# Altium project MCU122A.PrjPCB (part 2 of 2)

## Sheet MCU122A_WM2_ESD.SchDoc
size A3; Date: Not shown in title block; ApprovedBy: Not shown in title block; CheckedBy: Not shown in title block; Author: Not shown in title block; CompanyName: Not shown in title block; Engineer: Not shown in title block; Organization: Not shown in title block; Address1: Not shown in title block; Address2: Not shown in title block; Address3: Not shown in title block; Address4: Not shown in title block; DocumentNumber: 1; Revision: Use project parameter SCH_Rev; SheetNumber: 6; SheetTotal: 8; PageSetup: Record=PageOptions¦CenterHorizontal=True¦CenterVertical=True¦PrintScale=0.69¦XCorrection=1.00¦YCorrection=1.00¦PrintKind=0¦BorderSize=5000000¦LeftOffset=0¦BottomOffset=0¦Orientation=2¦PaperLength=1000¦PaperWidth=1000¦Scale=100¦PaperSource=15¦PrintQuality=600¦MediaType=1¦DitherType=10¦PaperKind=Letter¦PrintScaleMode=1
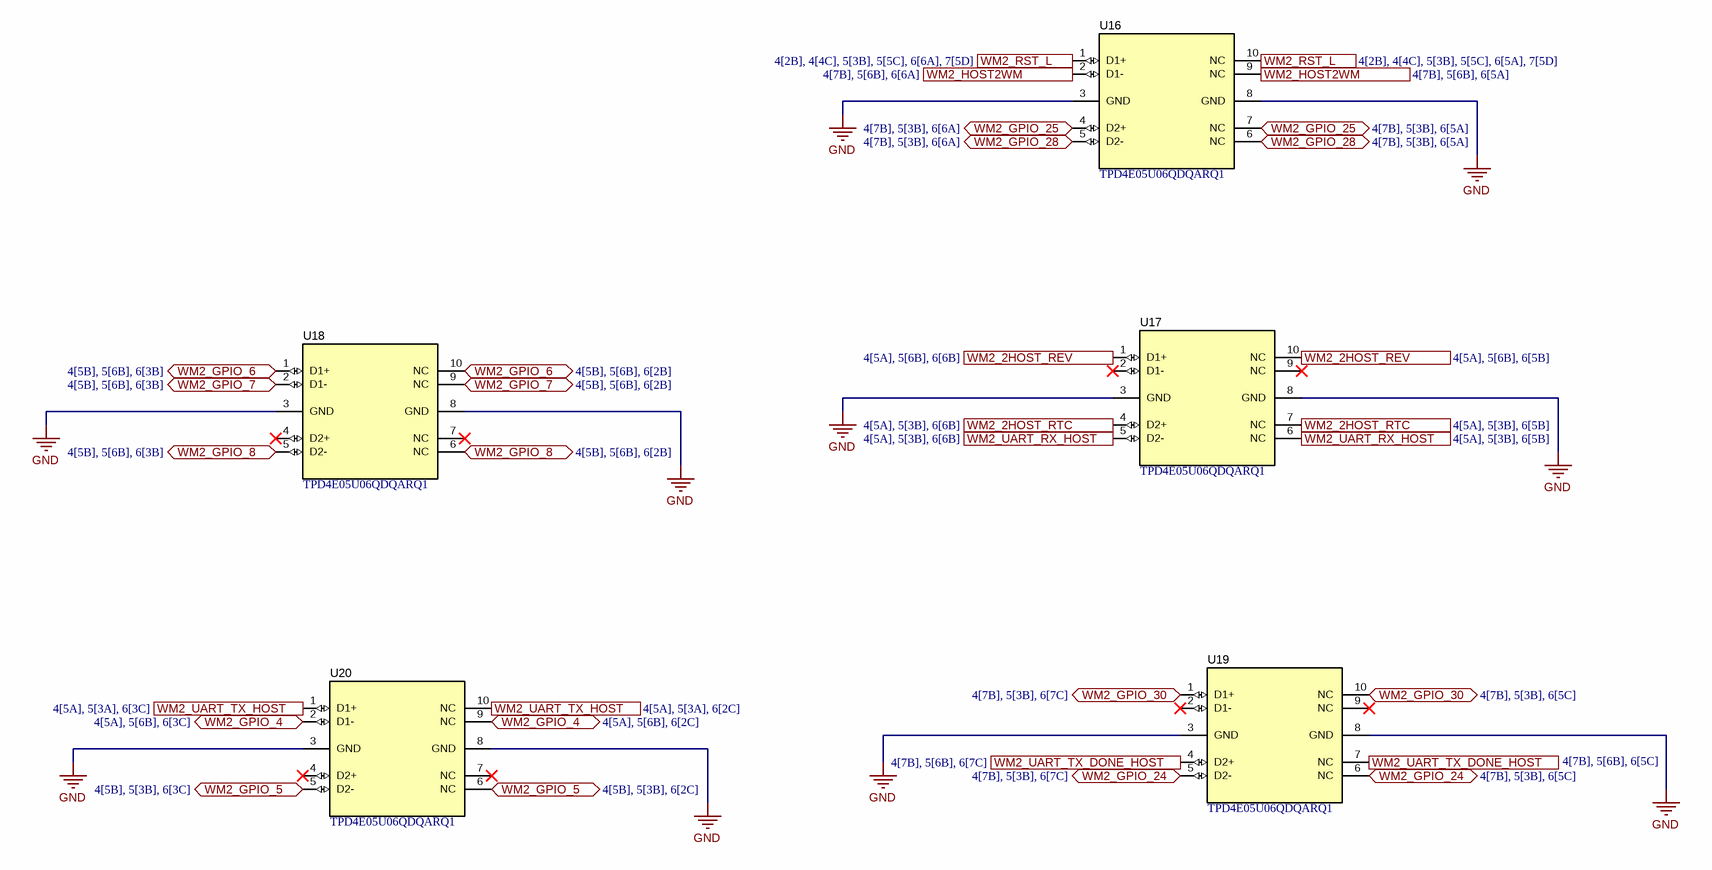
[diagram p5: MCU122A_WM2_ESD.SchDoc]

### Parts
U16  TPD4E05U06QDQARQ1  [DQA0010A]
U17  TPD4E05U06QDQARQ1  [DQA0010A]
U18  TPD4E05U06QDQARQ1  [DQA0010A]
U19  TPD4E05U06QDQARQ1  [DQA0010A]
U20  TPD4E05U06QDQARQ1  [DQA0010A]

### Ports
WM2_2HOST_REV (out, see 4[5A], 5[6B], 6[5B]), WM2_2HOST_REV (out, see 4[5A], 5[6B], 6[6B]), WM2_2HOST_RTC (out, see 4[5A], 5[3B], 6[5B]), WM2_2HOST_RTC (out, see 4[5A], 5[3B], 6[6B]), WM2_GPIO_4 (bidir, see 4[5A], 5[6B], 6[2C]), WM2_GPIO_4 (bidir, see 4[5A], 5[6B], 6[3C]), WM2_GPIO_5 (bidir, see 4[5B], 5[3B], 6[2C]), WM2_GPIO_5 (bidir, see 4[5B], 5[3B], 6[3C]), WM2_GPIO_6 (bidir, see 4[5B], 5[6B], 6[2B]), WM2_GPIO_6 (bidir, see 4[5B], 5[6B], 6[3B]), WM2_GPIO_7 (bidir, see 4[5B], 5[6B], 6[2B]), WM2_GPIO_7 (bidir, see 4[5B], 5[6B], 6[3B]), WM2_GPIO_8 (bidir, see 4[5B], 5[6B], 6[2B]), WM2_GPIO_8 (bidir, see 4[5B], 5[6B], 6[3B]), WM2_GPIO_24 (bidir, see 4[7B], 5[3B], 6[5C]), WM2_GPIO_24 (bidir, see 4[7B], 5[3B], 6[7C]), WM2_GPIO_25 (bidir, see 4[7B], 5[3B], 6[5A]), WM2_GPIO_25 (bidir, see 4[7B], 5[3B], 6[6A]), WM2_GPIO_28 (bidir, see 4[7B], 5[3B], 6[5A]), WM2_GPIO_28 (bidir, see 4[7B], 5[3B], 6[6A]), WM2_GPIO_30 (bidir, see 4[7B], 5[3B], 6[5C]), WM2_GPIO_30 (bidir, see 4[7B], 5[3B], 6[7C]), WM2_HOST2WM (out, see 4[7B], 5[6B], 6[5A]), WM2_HOST2WM (out, see 4[7B], 5[6B], 6[6A]), WM2_RST_L (out, see 4[2B], 4[4C], 5[3B], 5[5C], 6[5A], 7[5D]), WM2_RST_L (out, see 4[2B], 4[4C], 5[3B], 5[5C], 6[6A], 7[5D]), WM2_UART_RX_HOST (out, see 4[5A], 5[3B], 6[5B]), WM2_UART_RX_HOST (out, see 4[5A], 5[3B], 6[6B]), WM2_UART_TX_DONE_HOST (out, see 4[7B], 5[6B], 6[5C]), WM2_UART_TX_DONE_HOST (out, see 4[7B], 5[6B], 6[7C]), WM2_UART_TX_HOST (out, see 4[5A], 5[3A], 6[2C]), WM2_UART_TX_HOST (out, see 4[5A], 5[3A], 6[3C])

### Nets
GND: U16.3(GND) U16.8(GND) U17.3(GND) U17.8(GND) U18.3(GND) U18.8(GND) U19.3(GND) U19.8(GND) U20.3(GND) U20.8(GND)
WM2_2HOST_REV: U17.1(D1+) U17.10(NC) ; port WM2_2HOST_REV
WM2_2HOST_RTC: U17.4(D2+) U17.7(NC) ; port WM2_2HOST_RTC
WM2_GPIO_4: U20.2(D1-) U20.9(NC) ; port WM2_GPIO_4
WM2_GPIO_5: U20.5(D2-) U20.6(NC) ; port WM2_GPIO_5
WM2_GPIO_6: U18.1(D1+) U18.10(NC) ; port WM2_GPIO_6
WM2_GPIO_7: U18.2(D1-) U18.9(NC) ; port WM2_GPIO_7
WM2_GPIO_8: U18.5(D2-) U18.6(NC) ; port WM2_GPIO_8
WM2_GPIO_24: U19.5(D2-) U19.6(NC) ; port WM2_GPIO_24
WM2_GPIO_25: U16.4(D2+) U16.7(NC) ; port WM2_GPIO_25
WM2_GPIO_28: U16.5(D2-) U16.6(NC) ; port WM2_GPIO_28
WM2_GPIO_30: U19.1(D1+) U19.10(NC) ; port WM2_GPIO_30
WM2_HOST2WM: U16.2(D1-) U16.9(NC) ; port WM2_HOST2WM
WM2_RST_L: U16.1(D1+) U16.10(NC) ; port WM2_RST_L
WM2_UART_RX_HOST: U17.5(D2-) U17.6(NC) ; port WM2_UART_RX_HOST
WM2_UART_TX_DONE_HOST: U19.4(D2+) U19.7(NC) ; port WM2_UART_TX_DONE_HOST
WM2_UART_TX_HOST: U20.1(D1+) U20.10(NC) ; port WM2_UART_TX_HOST

Not connected (* = marked no-connect by the designer): U17 2(D1-)* 9(NC)*; U18 4(D2+)* 7(NC)*; U19 2(D1-)* 9(NC)*; U20 4(D2+)* 7(NC)*

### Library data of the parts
U16-U20 = CMP-0073599-3: Automotive 4-Channel ESD Protection Solution for SuperSpeed (up to 5 Gbps) Interface, DQA0010A (USON-10); Manufacturer: Texas Instruments; SizeZ_mm: 0.55; SizeX_mm: 1.0; SizeY_mm: 2.5; CompType: IC; SizeAreaWB_mm2: 7.0; AEC Category: Q200; AEC Qualified: Y

## Sheet MCU122A_Connector_PWR.SchDoc
size A3; Date: Not shown in title block; ApprovedBy: Not shown in title block; CheckedBy: Not shown in title block; Author: Not shown in title block; CompanyName: Not shown in title block; Engineer: Not shown in title block; Organization: Not shown in title block; Address1: Not shown in title block; Address2: Not shown in title block; Address3: Not shown in title block; Address4: Not shown in title block; DocumentNumber: 1; Revision: Use project parameter SCH_Rev; SheetNumber: 7; SheetTotal: 8; PageSetup: Record=PageOptions¦CenterHorizontal=True¦CenterVertical=True¦PrintScale=0.69¦XCorrection=1.00¦YCorrection=1.00¦PrintKind=0¦BorderSize=5000000¦LeftOffset=0¦BottomOffset=0¦Orientation=2¦PaperLength=1000¦PaperWidth=1000¦Scale=100¦PaperSource=15¦PrintQuality=600¦MediaType=1¦DitherType=10¦PaperKind=Letter¦PrintScaleMode=1
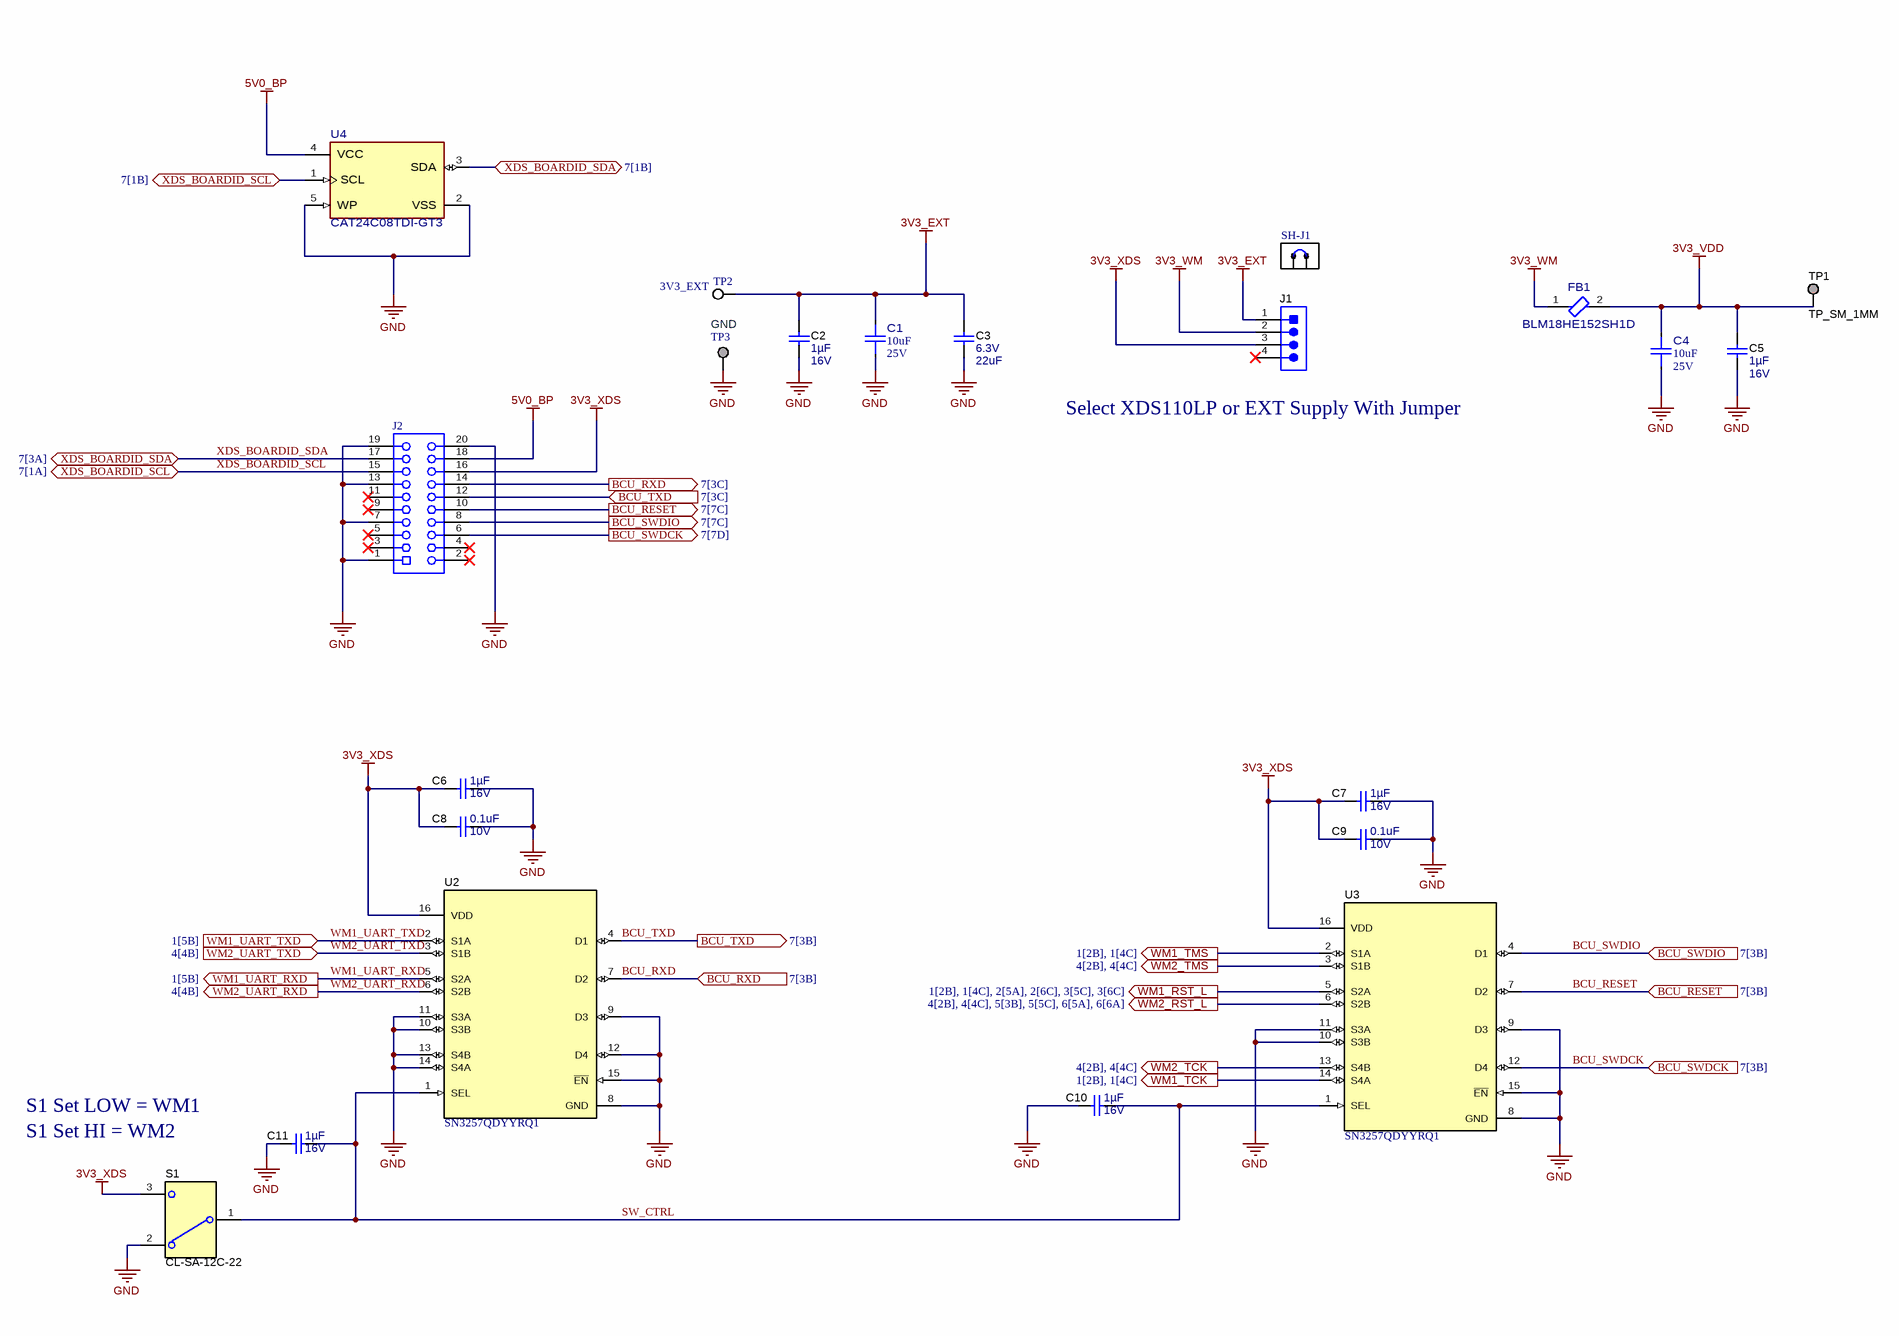
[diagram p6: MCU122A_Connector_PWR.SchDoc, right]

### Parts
C1  ValueDisplayed: 10uF  VDC_V: 25V  [FP-GCM32ER71E106MA57L_1210-MFG]  (hidden comment: GCM32ER71E106MA57L)
C2  Cap_F: 1µF  VDC_V: 16V  [0603]  (hidden comment: GCM188R71C105KA64D)
C3  VDC_V: 6.3V  ValueDisplayed: 22uF  [0805_HV]  (hidden comment: GCM21BD70J226ME36L)
C4  ValueDisplayed: 10uF  VDC_V: 25V  [FP-GCM32ER71E106MA57L_1210-MFG]  (hidden comment: GCM32ER71E106MA57L)
C5  Cap_F: 1µF  VDC_V: 16V  [0603]  (hidden comment: GCM188R71C105KA64D)
C6  Cap_F: 1µF  VDC_V: 16V  [0603]  (hidden comment: GCM188R71C105KA64D)
C7  Cap_F: 1µF  VDC_V: 16V  [0603]  (hidden comment: GCM188R71C105KA64D)
C8  VDC_V: 10V  ValueDisplayed: 0.1uF  [0402]  (hidden comment: GCM155R71A104KA55D)
C9  VDC_V: 10V  ValueDisplayed: 0.1uF  [0402]  (hidden comment: GCM155R71A104KA55D)
C10  Cap_F: 1µF  VDC_V: 16V  [0603]  (hidden comment: GCM188R71C105KA64D)
C11  Cap_F: 1µF  VDC_V: 16V  [0603]  (hidden comment: GCM188R71C105KA64D)
FB1  BLM18HE152SH1D  [FP-BLM18HE152SH1D_0603-MFG]
J1  TSW-104-07-G-S  [TSW-104-07-G-S]  (value not drawn)
J2  SFH11-PBPC-D10-RA-BK  [Sullins_SFH11-xxxC-D10-RA]  (value not drawn)
S1  CL-SA-12C-22  [SW_CL-SA-12C-22]
SH-J1  SNT-100-BK-G  [SNT-100-BK-G]  (value not drawn)
TP1  TP_SM_1MM  [TP_SM_1MM]  (no BOM)
TP2  Note: 3V3_EXT  [Keystone5012]  (hidden comment: 5012)
TP3  GND  [Keystone1598-2]
U2  SN3257QDYYRQ1  [DYY0016A]
U3  SN3257QDYYRQ1  [DYY0016A]
U4  CAT24C08TDI-GT3  [FP-CAT24C08TDI-GT3_TSOT-23-5-IPC_C]

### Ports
BCU_RESET (in, see 7[3B]), BCU_RESET (out, see 7[7C]), BCU_RXD (in, see 7[3B]), BCU_RXD (out, see 7[3C]), BCU_SWDCK (in, see 7[3B]), BCU_SWDCK (out, see 7[7D]), BCU_SWDIO (in, see 7[3B]), BCU_SWDIO (out, see 7[7C]), BCU_TXD (in, see 7[3C]), BCU_TXD (out, see 7[3B]), WM1_RST_L (out, see 1[2B], 1[4C], 2[5A], 2[6C], 3[5C], 3[6C]), WM1_TCK (out, see 1[2B], 1[4C]), WM1_TMS (out, see 1[2B], 1[4C]), WM1_UART_RXD (out, see 1[5B]), WM1_UART_TXD (in, see 1[5B]), WM2_RST_L (out, see 4[2B], 4[4C], 5[3B], 5[5C], 6[5A], 6[6A]), WM2_TCK (out, see 4[2B], 4[4C]), WM2_TMS (out, see 4[2B], 4[4C]), WM2_UART_RXD (out, see 4[4B]), WM2_UART_TXD (in, see 4[4B]), XDS_BOARDID_SCL (bidir, see 7[1A]), XDS_BOARDID_SCL (bidir, see 7[1B]), XDS_BOARDID_SDA (bidir, see 7[1B]), XDS_BOARDID_SDA (bidir, see 7[3A])

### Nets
3V3_EXT: C1.2 C2.1 C3.1 J1.1 TP2.1
3V3_VDD: C4.2 C5.1 FB1.2 TP1.1
3V3_WM: FB1.1 J1.2
3V3_XDS: C6.2 C7.2 C8.2 C9.2 J1.3 J2.16 S1.3 U2.16(VDD) U3.16(VDD)
5V0_BP: J2.18 U4.4(VCC)
GND: C1.1 C2.2 C3.2 C4.1 C5.2 C6.1 C7.1 C8.1 C9.1 C10.2 C11.2 J2.1 J2.7 J2.13 J2.19 J2.20 S1.2 TP3.1 U2.8(GND) U2.9(D3) U2.10(S3B) U2.11(S3A) U2.12(D4) U2.13(S4B) U2.14(S4A) U2.15(~{EN}) U3.8(GND) U3.9(D3) U3.10(S3B) U3.11(S3A) U3.15(~{EN}) U4.2(VSS) U4.5(WP)
BCU_RESET: J2.10 U3.7(D2) ; port BCU_RESET
BCU_RXD: J2.14 U2.7(D2) ; port BCU_RXD
BCU_SWDCK: J2.6 U3.12(D4) ; port BCU_SWDCK
BCU_SWDIO: J2.8 U3.4(D1) ; port BCU_SWDIO
BCU_TXD: J2.12 U2.4(D1) ; port BCU_TXD
SW_CTRL: C10.1 C11.1 S1.1 U2.1(SEL) U3.1(SEL)
WM1_RST_L: U3.5(S2A) ; port WM1_RST_L
WM1_TCK: U3.14(S4A) ; port WM1_TCK
WM1_TMS: U3.2(S1A) ; port WM1_TMS
WM1_UART_RXD: U2.5(S2A) ; port WM1_UART_RXD
WM1_UART_TXD: U2.2(S1A) ; port WM1_UART_TXD
WM2_RST_L: U3.6(S2B) ; port WM2_RST_L
WM2_TCK: U3.13(S4B) ; port WM2_TCK
WM2_TMS: U3.3(S1B) ; port WM2_TMS
WM2_UART_RXD: U2.6(S2B) ; port WM2_UART_RXD
WM2_UART_TXD: U2.3(S1B) ; port WM2_UART_TXD
XDS_BOARDID_SCL: J2.15 U4.1(SCL) ; port XDS_BOARDID_SCL
XDS_BOARDID_SDA: J2.17 U4.3(SDA) ; port XDS_BOARDID_SDA

Not connected (* = marked no-connect by the designer): J1 4*; J2 2* 3* 4* 5* 9* 11*

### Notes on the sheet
- (near J1) Select XDS110LP or EXT Supply With Jumper
- S1 Set LOW = WM1
- S1 Set HI = WM2

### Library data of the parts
C1 C4 = CMP-0037171-1: Ceramic Capacitor for Automotive 10uF ±20% 25VDC X7R 1210 Embossed T/R; Manufacturer: Murata; AEC Grade: Grade 1; AEC Qualified: Yes; Cap_F: 10µF; SizeZ_mm: 2.7mm; TempCo: 15%; Value: 10µF
C2 C5-C7 C10 C11 = CMP-0007136-5: CAP, CERM, 1 uF, 16 V, +/- 10%, X7R, AEC-Q200 Grade 1, 0603; Manufacturer: MuRata; TaMin_C: -55°C; Polarized: N; SizeAreaWB_mm2: 4.68; Value1: Unknown; U/M: EA; Value: 1uF; TaMax_C: 125°C; SizeZ_mm: 1; SizeX_mm: 1.6; SizeY_mm: 0.8; SizeArea_mm2: 1.28; AEC Qualified: Y; AEC Category: Q200
C3 = CMP-0008015-1: CAP, CERM, 22 uF, 6.3 V, +/- 20%, X7T, AEC-Q200 Grade 1, 0805; Manufacturer: MuRata; TaMin_C: -55°C; Polarized: N; SizeAreaWB_mm2: 6.75; Value1: Unknown; U/M: EA; Value: 22uF; TaMax_C: 125°C; SizeZ_mm: 1.45; SizeX_mm: 2; SizeY_mm: 1.25; Cap_Case: 0805; SizeArea_mm2: 2.5; AEC Qualified: Y; Cap_F: 22µF; AEC Grade: 1; AEC Category: Q200
C8 C9 = CMP-0006350-2: CAP, CERM, 0.1 uF, 10 V, +/- 10%, X7R, AEC-Q200 Grade 1, 0402; Manufacturer: MuRata; TaMin_C: -55°C; Polarized: N; SizeAreaWB_mm2: 3; Value1: Unknown; U/M: EA; Value: 0.1uF; TaMax_C: 125°C; SizeZ_mm: 0.6; SizeX_mm: 1; SizeY_mm: 0.5; AEC Qualified: Y; Cap_F: 100nF; AEC Category: Q200
FB1 = CMP-0092703-1: Chip Ferrite Bead, 0603, 1500Ω @ 100MHz, 0.5Ω, 25%, 500mA; Manufacturer: Murata; AEC Grade: Grade 1; AEC Qualified: Yes; SizeZ_mm: 0.95mm; DCR_ohm: 0.5
J1 = CMP-0075409-2: Header, 100mil, 4x1, Gold, TH; Manufacturer: Samtec; Pitch_mm: 2.54; Cert_VDE: N; Gender: Male; Cert_CSA: Y; Voltage_V: 550V; Green_REACh: Passed; Current_A: 6.3A; Green_Lifecycle: Active; Row_Count: 1
J2 = CMP-0074634-1: Receptacle, 2.54mm, 10x2, Gold, R/A, TH; Manufacturer: Sullins Connector Solutions; CNHeader: False; Current_A: 3A; Gender: Female; Voltage_V: 1kV; CompType: Socket Strip; Row_Count: 2; Pitch_mm: 2.54; CT: True; Cert_UL: Y
S1 = CMP-0078235-1: Switch, SPDT, On-On, 0.5 A, 12 VDC, TH; Manufacturer: NIDEC SEIMITSU; SizeAreaWB_mm2: 54.48; SizeArea_mm2: 25.4; SizeZ_mm: 6.7; SizeY_mm: 2.54; VDC_V: 12V; CurrentRating_mA: 500A; PositionCount: 2; SizeX_mm: 10
SH-J1 = CMP-0003623-3: Shunt, 100mil, Gold plated, Black; Alternate PartNumber: 969102-0000-DA; Manufacturer: Samtec; Alternate Manufacturer: 3M; Value: 1x2; Note: You can "mate" this to a header by matching the designator.  i.e. use SH-J3 for header J3
TP1 = CMP-0003825-1: 1mm Test Point, SMT; Manufacturer: Any
TP2 = CMP-0055149-2: Test Point, Multipurpose, White, TH; Manufacturer: Keystone Electronics; ContactFinish: Silver; CNHeader: FALSE; Green_Lifecycle: Active; Green_REACh: Passed; CT: TRUE
TP3 = CMP-0055121-1: Terminal, Turret, TH, Triple; Manufacturer: Keystone; PartNumber: 1598-2; CT: FALSE; Green_REACh: Passed; CompType: Turret Terminal; Green_Lifecycle: Active
U2 U3 = CMP-0860151-2: SN3257QDYYRQ1, DYY0016A (SOT-23-THIN-16); Manufacturer: Texas Instruments; SizeX_mm: 3.26; SizeArea_mm2: 13.692; SizeAreaWB_mm2: 22.152; AEC Qualified: Y; CompType: IC; SizeZ_mm: 1.1; AEC Category: Q200; SizeY_mm: 4.2
U4 = CMP-0087170-1: 8KB I2C SER EEPROM TSOT 23; Manufacturer: ON Semiconductor; SizeZ_mm: 1mm

## Sheet MCU122A_Hardware.SchDoc
size A3; Date: Not shown in title block; ApprovedBy: Not shown in title block; CheckedBy: Not shown in title block; Author: Not shown in title block; CompanyName: Not shown in title block; Engineer: Not shown in title block; Organization: Not shown in title block; Address1: Not shown in title block; Address2: Not shown in title block; Address3: Not shown in title block; Address4: Not shown in title block; DocumentNumber: 1; Revision: Use project parameter SCH_Rev; SheetNumber: 8; SheetTotal: 8; PageSetup: Record=PageOptions¦CenterHorizontal=True¦CenterVertical=True¦PrintScale=0.69¦XCorrection=1.00¦YCorrection=1.00¦PrintKind=0¦BorderSize=5000000¦LeftOffset=0¦BottomOffset=0¦Orientation=2¦PaperLength=1000¦PaperWidth=1000¦Scale=100¦PaperSource=15¦PrintQuality=600¦MediaType=1¦DitherType=10¦PaperKind=Letter¦PrintScaleMode=1
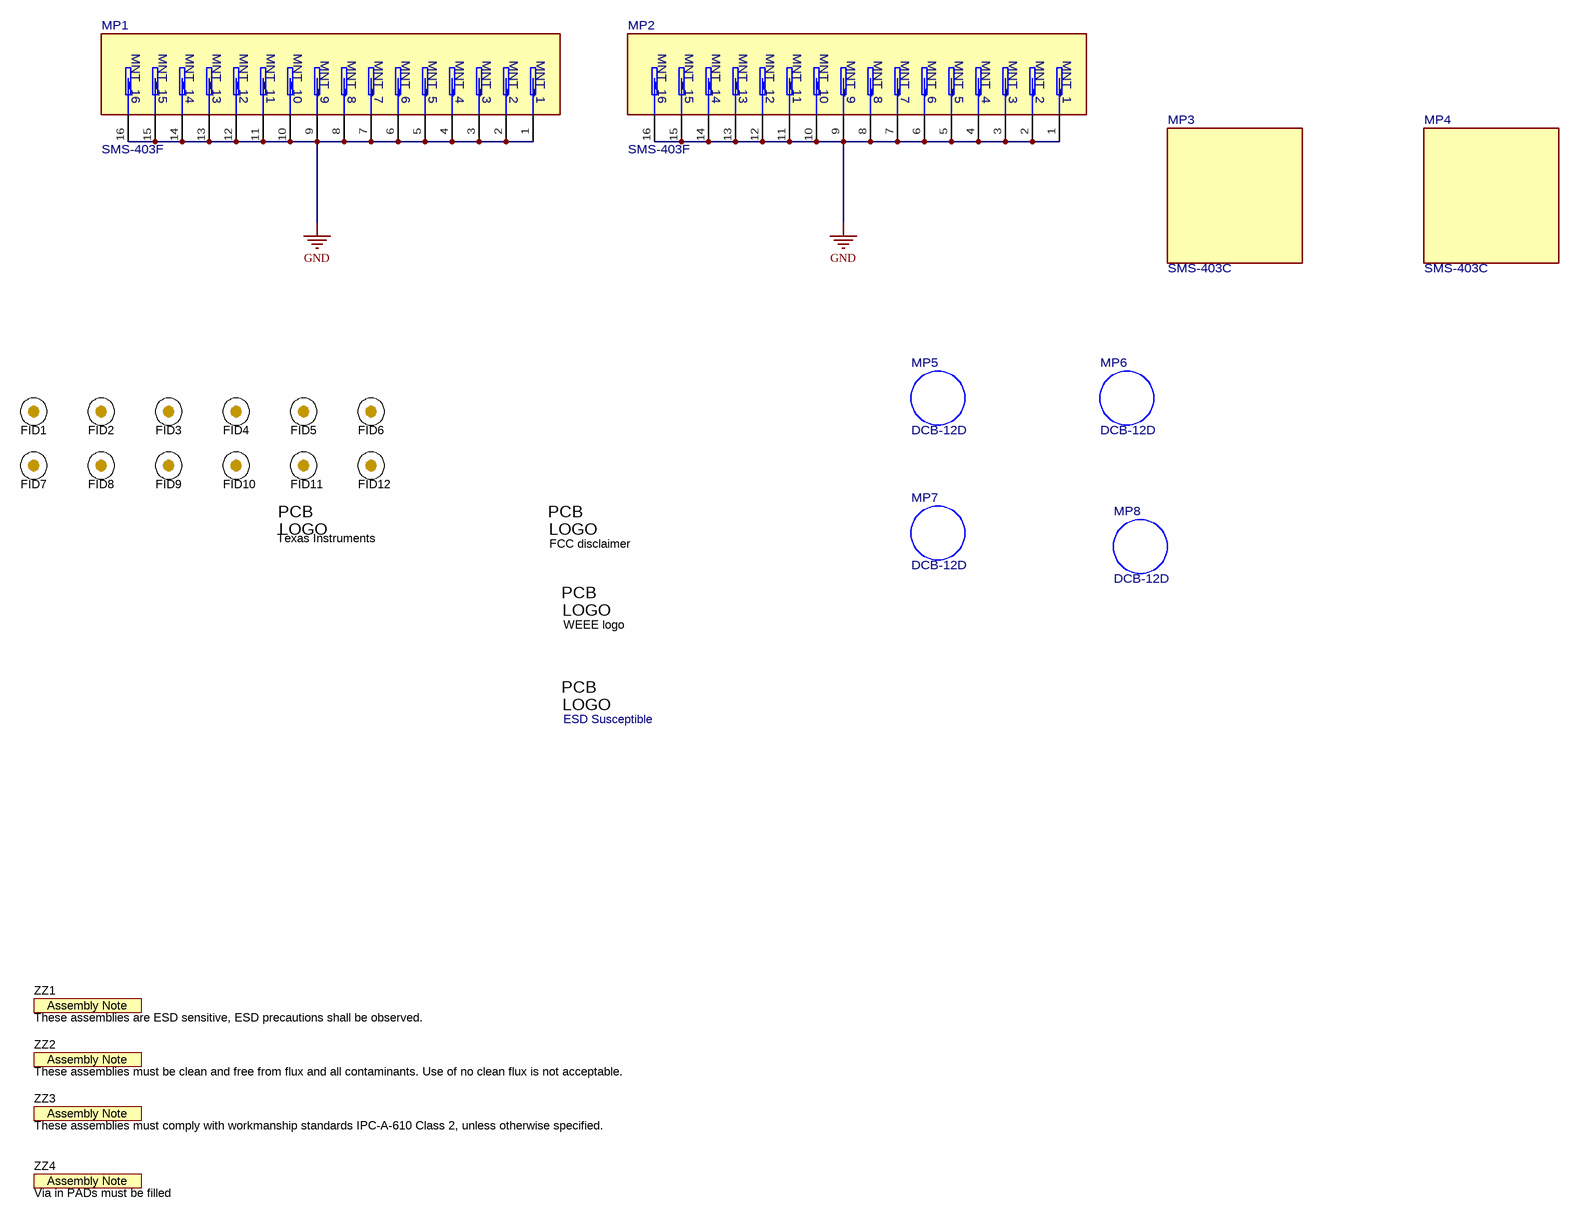
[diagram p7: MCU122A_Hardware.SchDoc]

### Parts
FID1  Fiducial  [Fiducial10-20]  (value not drawn)  (no BOM)
FID2  Fiducial  [Fiducial10-20]  (value not drawn)  (no BOM)
FID3  Fiducial  [Fiducial10-20]  (value not drawn)  (no BOM)
FID4  Fiducial  [Fiducial10-20]  (value not drawn)  (no BOM)
FID5  Fiducial  [Fiducial10-20]  (value not drawn)  (no BOM)
FID6  Fiducial  [Fiducial10-20]  (value not drawn)  (no BOM)
FID7  Fiducial  [Fiducial10-20]  (value not drawn)  (no BOM)
FID8  Fiducial  [Fiducial10-20]  (value not drawn)  (no BOM)
FID9  Fiducial  [Fiducial10-20]  (value not drawn)  (no BOM)
FID10  Fiducial  [Fiducial10-20]  (value not drawn)  (no BOM)
FID11  Fiducial  [Fiducial10-20]  (value not drawn)  (no BOM)
FID12  Fiducial  [Fiducial10-20]  (value not drawn)  (no BOM)
Logo1  Texas Instruments  [TI_Stacked_Overlay_Small]  (no BOM)
Logo3  FCC disclaimer  [FCC_disclaimer]  (no BOM)
Logo4  WEEE logo  [WEEE_Minimum]  (no BOM)
Logo5  ESD Susceptible  [ESD_Overlay_Medium]  (no BOM)
MP1  SMS-403F  [FP-SMS-403F_SMT_SHIELD-MFG]
MP2  SMS-403F  [FP-SMS-403F_SMT_SHIELD-MFG]
MP3  SMS-403C  [FP-SMS-403C_RF_SHLD-MFG]
MP4  SMS-403C  [FP-SMS-403C_RF_SHLD-MFG]
MP5  DCB-12D  [FP-DCB-12D_SPACER-MFG]
MP6  DCB-12D  [FP-DCB-12D_SPACER-MFG]
MP7  DCB-12D  [FP-DCB-12D_SPACER-MFG]
MP8  DCB-12D  [FP-DCB-12D_SPACER-MFG]
ZZ1  These assemblies are ESD sensitive, ESD precautions shall be observed.  [AssemblyNote]  (no BOM)
ZZ2  These assemblies must be clean and free from flux and all contaminants. Use of no clean flux is not acceptable.  [AssemblyNote]  (no BOM)
ZZ3  These assemblies must comply with workmanship standards IPC-A-610 Class 2, unless otherwise specified.  [AssemblyNote]  (no BOM)
ZZ4  Via in PADs must be filled  [AssemblyNote]  (no BOM)

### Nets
GND: MP1.1(MNT_1) MP1.2(MNT_2) MP1.3(MNT_3) MP1.4(MNT_4) MP1.5(MNT_5) MP1.6(MNT_6) MP1.7(MNT_7) MP1.8(MNT_8) MP1.9(MNT_9) MP1.10(MNT_10) MP1.11(MNT_11) MP1.12(MNT_12) MP1.13(MNT_13) MP1.14(MNT_14) MP1.15(MNT_15) MP1.16(MNT_16) MP2.1(MNT_1) MP2.2(MNT_2) MP2.3(MNT_3) MP2.4(MNT_4) MP2.5(MNT_5) MP2.6(MNT_6) MP2.7(MNT_7) MP2.8(MNT_8) MP2.9(MNT_9) MP2.10(MNT_10) MP2.11(MNT_11) MP2.12(MNT_12) MP2.13(MNT_13) MP2.14(MNT_14) MP2.15(MNT_15) MP2.16(MNT_16)

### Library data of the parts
FID1-FID12 = CMP-0077181-1: Fiducial mark.  There is nothing to buy or mount.
Logo1 = CMP-0074838-1: Texas Instrument Corporate Signature; SymbolCreator: a0412235; Lib Reference: TI_Logo; Library Reference: Logo
Logo3 = CMP-0074847-1: FCC_disclaimer; Library Reference: Logo
Logo4 = CMP-0074769-4: Manufacturer: Texas Instruments; CompType: IC; AEC Category: Q200
Logo5 = CMP-0074840-1: ESD Susceptible Symbol; SymbolCreator: a0412235; Lib Reference: ESD_Susceptible
MP1 MP2 = CMP-0086879-1: RF SHIELD 1.034" X 1.034" SMD; Manufacturer: Leader Tech
MP3 MP4 = CMP-0120478-1: RF Shield Cover 1.058" (26.87mm) X 1.058" (26.87mm) Non-Vented Surface Mount; Manufacturer: Leader Tech; AEC Qualified: No; SizeZ_mm: 0.084inch
MP5-MP8 = CMP-0016301-1: Spacer Support Nylon 66 Natural; Manufacturer: Kang Yang USA; AEC Qualified: No
ZZ1 = CMP-0077236-1
ZZ2 = CMP-0077237-1
ZZ3 = CMP-0077238-1
ZZ4 = CMP-0077238-1: These assemblies must comply with workmanship standards IPC-A-610 Class 2, unless otherwise specified.

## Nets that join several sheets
3V3_EXT: MCU122A_WM1_GPIO_Header (J7.25), MCU122A_WM2_GPIO_Header (J14.25), MCU122A_Connector_PWR (5 pins)
3V3_VDD: MCU122A_WM1 (J6.1), MCU122A_WM2 (J13.1), MCU122A_Connector_PWR (C4.2 C5.1 FB1.2 TP1.1)
GND: MCU122A_WM1 (48 pins), MCU122A_WM1_GPIO_Header (13 pins), MCU122A_WM1_ESD (12 pins), MCU122A_WM2 (48 pins), MCU122A_WM2_GPIO_Header (13 pins), MCU122A_WM2_ESD (10 pins), MCU122A_Connector_PWR (33 pins), MCU122A_Hardware (32 pins)
WM1_VDD: MCU122A_WM1 (6 pins), MCU122A_WM1_GPIO_Header (J9.1)
WM2_VDD: MCU122A_WM2 (6 pins), MCU122A_WM2_GPIO_Header (J16.1)
WM1_2HOST_REV: MCU122A_WM1 (R1.2), MCU122A_WM1_GPIO_Header (J7.17), MCU122A_WM1_ESD (U13.5 U13.6)
WM1_2HOST_RTC: MCU122A_WM1 (R2.2), MCU122A_WM1_GPIO_Header (J7.20), MCU122A_WM1_ESD (U10.5 U10.6)
WM1_GPIO_4: MCU122A_WM1 (R5.2), MCU122A_WM1_GPIO_Header (J7.23), MCU122A_WM1_ESD (U11.2 U11.9)
WM1_GPIO_5: MCU122A_WM1 (R6.2), MCU122A_WM1_GPIO_Header (J7.1), MCU122A_WM1_ESD (U15.5 U15.6)
WM1_GPIO_6: MCU122A_WM1 (R7.2), MCU122A_WM1_GPIO_Header (J7.13), MCU122A_WM1_ESD (U11.5 U11.6)
WM1_GPIO_7: MCU122A_WM1 (R8.2), MCU122A_WM1_GPIO_Header (J7.11), MCU122A_WM1_ESD (U12.1 U12.10)
WM1_GPIO_8: MCU122A_WM1 (R9.2), MCU122A_WM1_GPIO_Header (J7.16), MCU122A_WM1_ESD (U13.2 U13.9)
WM1_GPIO_24: MCU122A_WM1 (R14.2), MCU122A_WM1_GPIO_Header (J7.8), MCU122A_WM1_ESD (U14.2 U14.9)
WM1_GPIO_25: MCU122A_WM1 (R15.2), MCU122A_WM1_GPIO_Header (J7.3), MCU122A_WM1_ESD (U15.1 U15.10)
WM1_GPIO_28: MCU122A_WM1 (R16.2), MCU122A_WM1_GPIO_Header (J7.10), MCU122A_WM1_ESD (U12.5 U12.6)
WM1_GPIO_30: MCU122A_WM1 (R18.2), MCU122A_WM1_GPIO_Header (J7.14), MCU122A_WM1_ESD (U13.1 U13.10)
WM1_HOST2WM: MCU122A_WM1 (R13.2), MCU122A_WM1_GPIO_Header (J7.24), MCU122A_WM1_ESD (U10.1 U10.10)
WM1_RST_L: MCU122A_WM1 (6 pins), MCU122A_WM1_GPIO_Header (J7.4 J8.2), MCU122A_WM1_ESD (U15.4 U15.7), MCU122A_Connector_PWR (U3.5)
WM1_TCK: MCU122A_WM1 (5 pins), MCU122A_Connector_PWR (U3.14)
WM1_TMS: MCU122A_WM1 (5 pins), MCU122A_Connector_PWR (U3.2)
WM1_UART_RX_HOST: MCU122A_WM1 (R3.2), MCU122A_WM1_GPIO_Header (J7.22), MCU122A_WM1_ESD (U11.1 U11.10)
WM1_UART_RXD: MCU122A_WM1 (U1.18), MCU122A_Connector_PWR (U2.5)
WM1_UART_TX_DONE_HOST: MCU122A_WM1 (R17.2), MCU122A_WM1_GPIO_Header (J7.7), MCU122A_WM1_ESD (U14.5 U14.6)
WM1_UART_TX_HOST: MCU122A_WM1 (R4.2), MCU122A_WM1_GPIO_Header (J7.19), MCU122A_WM1_ESD (U10.4 U10.7)
WM1_UART_TXD: MCU122A_WM1 (U1.17), MCU122A_Connector_PWR (U2.2)
WM1_WD_SET0: MCU122A_WM1 (U1.31), MCU122A_WM1_GPIO_Header (R22.1 U6.1)
WM1_WD_SET1: MCU122A_WM1 (U1.21), MCU122A_WM1_GPIO_Header (R24.2 U6.5)
WM1_WDI: MCU122A_WM1 (U1.20), MCU122A_WM1_GPIO_Header (R23.2 U6.6)
WM2_2HOST_REV: MCU122A_WM2 (R25.2), MCU122A_WM2_GPIO_Header (J14.16), MCU122A_WM2_ESD (U17.1 U17.10)
WM2_2HOST_RTC: MCU122A_WM2 (R26.2), MCU122A_WM2_GPIO_Header (J14.13), MCU122A_WM2_ESD (U17.4 U17.7)
WM2_GPIO_4: MCU122A_WM2 (R29.2), MCU122A_WM2_GPIO_Header (J14.4), MCU122A_WM2_ESD (U20.2 U20.9)
WM2_GPIO_5: MCU122A_WM2 (R30.2), MCU122A_WM2_GPIO_Header (J14.9), MCU122A_WM2_ESD (U20.5 U20.6)
WM2_GPIO_6: MCU122A_WM2 (R31.2), MCU122A_WM2_GPIO_Header (J14.8), MCU122A_WM2_ESD (U18.1 U18.10)
WM2_GPIO_7: MCU122A_WM2 (R32.2), MCU122A_WM2_GPIO_Header (J14.10), MCU122A_WM2_ESD (U18.2 U18.9)
WM2_GPIO_8: MCU122A_WM2 (R33.2), MCU122A_WM2_GPIO_Header (J14.14), MCU122A_WM2_ESD (U18.5 U18.6)
WM2_GPIO_24: MCU122A_WM2 (R38.2), MCU122A_WM2_GPIO_Header (J14.3), MCU122A_WM2_ESD (U19.5 U19.6)
WM2_GPIO_25: MCU122A_WM2 (R39.2), MCU122A_WM2_GPIO_Header (J14.23), MCU122A_WM2_ESD (U16.4 U16.7)
WM2_GPIO_28: MCU122A_WM2 (R40.2), MCU122A_WM2_GPIO_Header (J14.17), MCU122A_WM2_ESD (U16.5 U16.6)
WM2_GPIO_30: MCU122A_WM2 (R42.2), MCU122A_WM2_GPIO_Header (J14.7), MCU122A_WM2_ESD (U19.1 U19.10)
WM2_HOST2WM: MCU122A_WM2 (R37.2), MCU122A_WM2_GPIO_Header (J14.24), MCU122A_WM2_ESD (U16.2 U16.9)
WM2_RST_L: MCU122A_WM2 (6 pins), MCU122A_WM2_GPIO_Header (J14.19 J15.2), MCU122A_WM2_ESD (U16.1 U16.10), MCU122A_Connector_PWR (U3.6)
WM2_TCK: MCU122A_WM2 (5 pins), MCU122A_Connector_PWR (U3.13)
WM2_TMS: MCU122A_WM2 (5 pins), MCU122A_Connector_PWR (U3.3)
WM2_UART_RX_HOST: MCU122A_WM2 (R27.2), MCU122A_WM2_GPIO_Header (J14.11), MCU122A_WM2_ESD (U17.5 U17.6)
WM2_UART_RXD: MCU122A_WM2 (U7.18), MCU122A_Connector_PWR (U2.6)
WM2_UART_TX_DONE_HOST: MCU122A_WM2 (R41.2), MCU122A_WM2_GPIO_Header (J14.6), MCU122A_WM2_ESD (U19.4 U19.7)
WM2_UART_TX_HOST: MCU122A_WM2 (R28.2), MCU122A_WM2_GPIO_Header (J14.1), MCU122A_WM2_ESD (U20.1 U20.10)
WM2_UART_TXD: MCU122A_WM2 (U7.17), MCU122A_Connector_PWR (U2.3)
WM2_WD_SET0: MCU122A_WM2 (U7.31), MCU122A_WM2_GPIO_Header (R46.1 U9.1)
WM2_WD_SET1: MCU122A_WM2 (U7.21), MCU122A_WM2_GPIO_Header (R48.2 U9.5)
WM2_WDI: MCU122A_WM2 (U7.20), MCU122A_WM2_GPIO_Header (R47.2 U9.6)
WM2WM_SF_INT: MCU122A_WM1 (TP9.1 U1.36), MCU122A_WM2 (U7.36)
WM2WM_SPI_CS: MCU122A_WM1 (TP8.1 U1.29), MCU122A_WM2 (U7.29)
WM2WM_SPI_MISO: MCU122A_WM1 (TP10.1 U1.39), MCU122A_WM2 (U7.39)
WM2WM_SPI_MOSI: MCU122A_WM1 (TP7.1 U1.28), MCU122A_WM2 (U7.28)
WM2WM_SPI_SCK: MCU122A_WM1 (TP6.1 U1.26), MCU122A_WM2 (U7.26)
WM2WM_SRDY: MCU122A_WM1 (TP11.1 U1.40), MCU122A_WM2 (U7.40)

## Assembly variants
001: not fitted C12 C13 C14 C15 C16 C17 C18 C19 C20 C29 C30 C31 C32 C33 C34 C37 C38 C39 C46 C52 C53 C54 C55 C56 C57 C58 C59 C60 C69 C70 C71 C72 C73 C74 C77 C78 C79 C86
